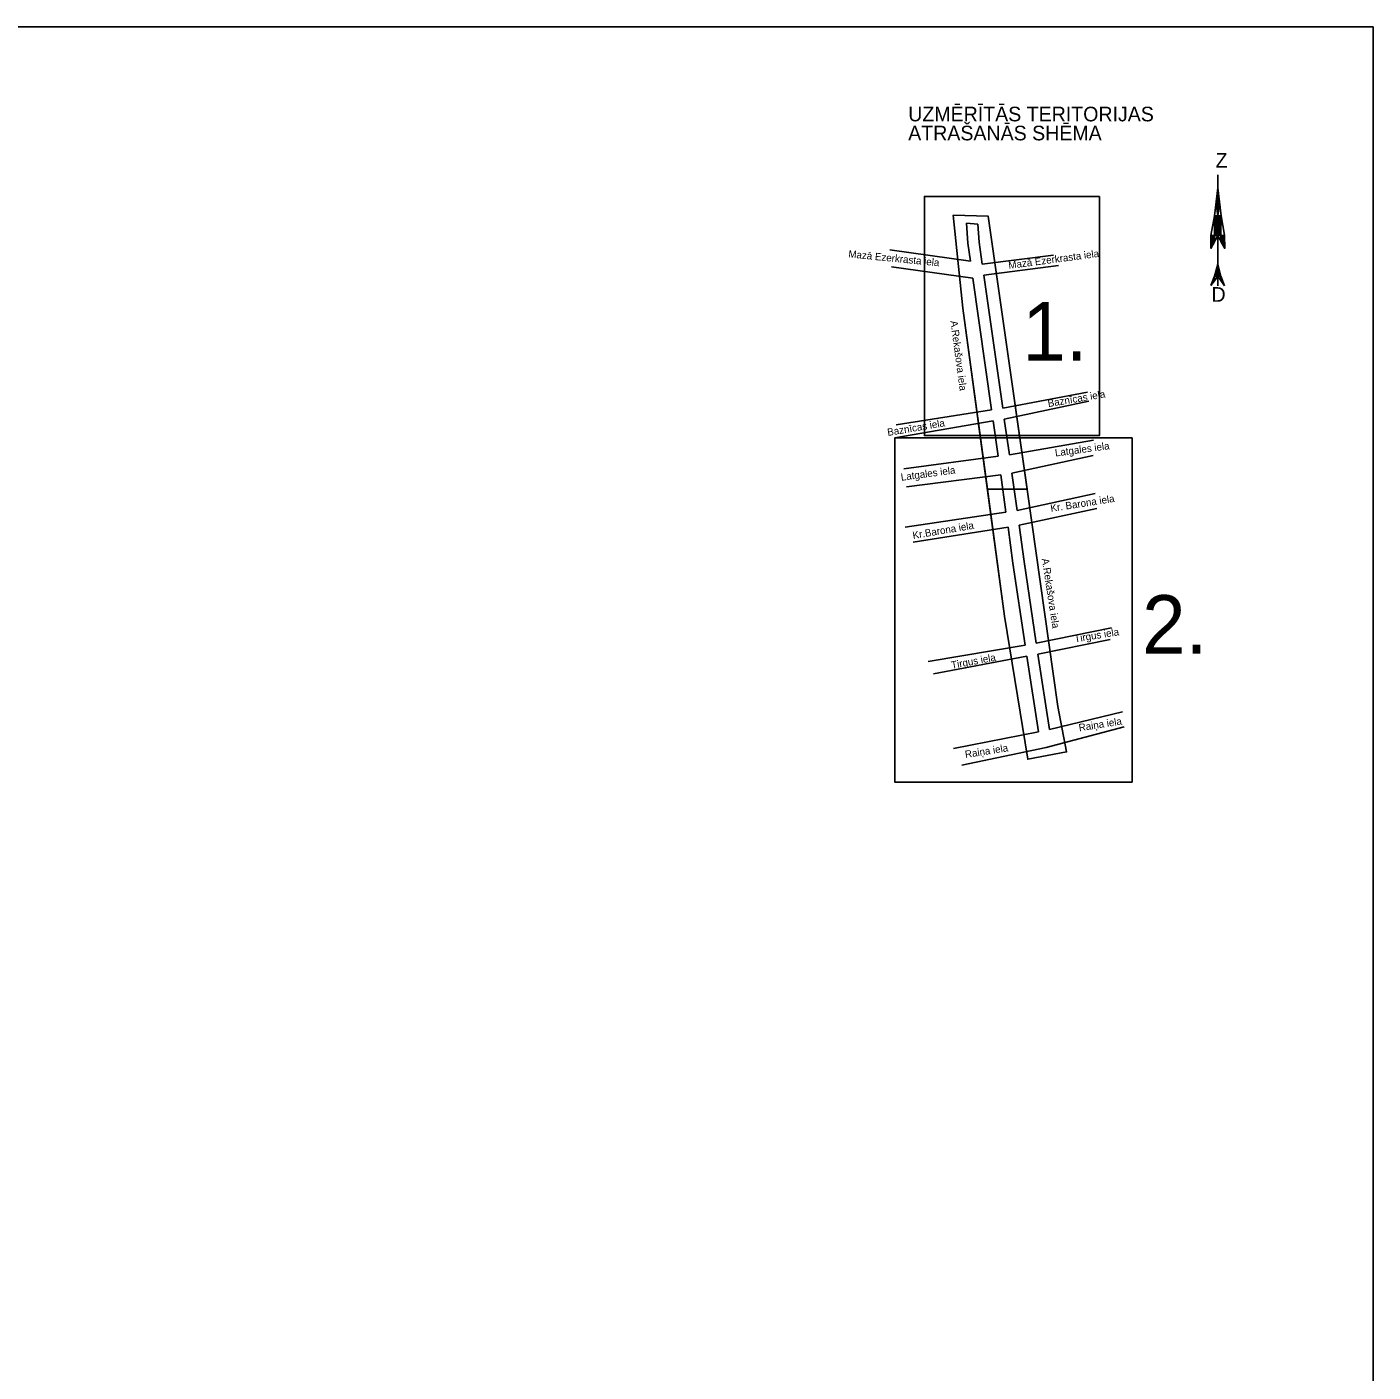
# Model space of a CAD drawing. Extents: x 728710 to 728960, y 272811 to 273475.
# Drawn here: x 728820.9 to 728912.9, y 273383.2 to 273475.1 of the extents above; entities that cross this region are included whole.
import ezdxf

# ---------------------------------------------------------------- set-up
doc = ezdxf.new("R2010")
doc.units = 0
doc.layers.add('RAMI_PLAN_####_TKST_#', color=7, linetype='Continuous')

msp = doc.modelspace()

# ---------------------------------------------------------------- linework, layer by layer
at = {"layer": 'RAMI_PLAN_####_TKST_#'}
for p, q in [((728902.305, 273465.008), (728902.305, 273464.128)), ((728902.087, 273462.204), (728902.305, 273464.12)), ((728902.305, 273464.12), (728902.181, 273463.03)), ((728902.268, 273463.788), (728902.335, 273463.855)), ((728902.275, 273463.851), (728902.329, 273463.906)), ((728902.282, 273463.915), (728902.324, 273463.957)), ((728902.289, 273463.979), (728902.318, 273464.008)), ((728902.297, 273464.043), (728902.312, 273464.059)), ((728902.304, 273464.107), (728902.307, 273464.11)), ((728902.305, 273464.12), (728902.52, 273462.209)), ((728902.428, 273463.033), (728902.305, 273464.12)), ((728902.303, 273462.206), (728902.181, 273463.03)), ((728902.181, 273463.03), (728902.303, 273462.206)), ((728902.182, 273463.023), (728902.404, 273463.245)), ((728902.187, 273463.085), (728902.398, 273463.296)), ((728902.189, 273462.974), (728902.41, 273463.194)), ((728902.195, 273463.149), (728902.392, 273463.347)), ((728902.197, 273462.925), (728902.415, 273463.143)), ((728902.202, 273463.213), (728902.387, 273463.398)), ((728902.204, 273462.875), (728902.421, 273463.093)), ((728902.209, 273463.277), (728902.381, 273463.449)), ((728902.211, 273462.826), (728902.427, 273463.042)), ((728902.216, 273463.341), (728902.375, 273463.499)), ((728902.218, 273462.777), (728902.419, 273462.978)), ((728902.224, 273463.404), (728902.37, 273463.55)), ((728902.231, 273463.468), (728902.364, 273463.601)), ((728902.238, 273463.532), (728902.358, 273463.652)), ((728902.246, 273463.596), (728902.352, 273463.703)), ((728902.253, 273463.66), (728902.347, 273463.754)), ((728902.26, 273463.724), (728902.341, 273463.804)), ((728902.428, 273463.033), (728902.303, 273462.206)), ((728902.303, 273462.206), (728902.428, 273463.033)), ((728901.82, 273460.867), (728902.087, 273462.204)), ((728902.087, 273462.204), (728902.077, 273460.888)), ((728902.084, 273461.875), (728902.302, 273462.093)), ((728902.084, 273461.818), (728902.302, 273462.037)), ((728902.085, 273462.046), (728902.245, 273462.206)), ((728902.085, 273461.989), (728902.302, 273462.206)), ((728902.085, 273461.932), (728902.302, 273462.15)), ((728902.086, 273462.103), (728902.188, 273462.205)), ((728902.086, 273462.16), (728902.13, 273462.204)), ((728902.087, 273462.204), (728902.303, 273462.206)), ((728902.226, 273462.728), (728902.409, 273462.911)), ((728902.233, 273462.678), (728902.399, 273462.844)), ((728902.24, 273462.629), (728902.389, 273462.778)), ((728902.247, 273462.58), (728902.379, 273462.711)), ((728902.255, 273462.53), (728902.369, 273462.644)), ((728902.262, 273462.481), (728902.359, 273462.578)), ((728902.269, 273462.432), (728902.349, 273462.511)), ((728902.277, 273462.382), (728902.339, 273462.444)), ((728902.284, 273462.333), (728902.328, 273462.378)), ((728902.291, 273462.284), (728902.318, 273462.311)), ((728902.298, 273462.235), (728902.308, 273462.245)), ((728902.303, 273462.206), (728902.298, 273457.431)), ((728902.302, 273462.135), (728902.52, 273461.917)), ((728902.302, 273462.078), (728902.52, 273461.86)), ((728902.302, 273462.021), (728902.52, 273461.804)), ((728902.303, 273462.206), (728902.52, 273462.209)), ((728902.303, 273462.191), (728902.52, 273461.973)), ((728902.343, 273462.207), (728902.52, 273462.03)), ((728902.399, 273462.208), (728902.52, 273462.086)), ((728902.455, 273462.208), (728902.52, 273462.143)), ((728902.511, 273462.209), (728902.52, 273462.199)), ((728902.52, 273462.209), (728902.519, 273460.884)), ((728902.52, 273462.209), (728902.763, 273460.879)), ((728885.896, 273461.644), (728885.121, 273461.699)), ((728902.077, 273460.907), (728902.301, 273461.131)), ((728902.078, 273461.021), (728902.302, 273461.244)), ((728902.078, 273460.964), (728902.301, 273461.187)), ((728902.079, 273461.192), (728902.302, 273461.414)), ((728902.079, 273461.135), (728902.302, 273461.357)), ((728902.079, 273461.078), (728902.302, 273461.301)), ((728902.08, 273461.306), (728902.302, 273461.527)), ((728902.08, 273461.249), (728902.302, 273461.47)), ((728902.081, 273461.476), (728902.302, 273461.697)), ((728902.081, 273461.419), (728902.302, 273461.64)), ((728902.081, 273461.362), (728902.302, 273461.584)), ((728902.082, 273461.59), (728902.302, 273461.81)), ((728902.082, 273461.533), (728902.302, 273461.754)), ((728902.083, 273461.761), (728902.302, 273461.98)), ((728902.083, 273461.704), (728902.302, 273461.923)), ((728902.083, 273461.647), (728902.302, 273461.867)), ((728902.301, 273461.174), (728902.519, 273460.956)), ((728902.301, 273461.117), (728902.519, 273460.9)), ((728902.302, 273461.965), (728902.52, 273461.747)), ((728902.302, 273461.908), (728902.52, 273461.691)), ((728902.302, 273461.852), (728902.52, 273461.634)), ((728902.302, 273461.795), (728902.52, 273461.578)), ((728902.302, 273461.739), (728902.52, 273461.521)), ((728902.302, 273461.682), (728902.52, 273461.465)), ((728902.302, 273461.626), (728902.519, 273461.408)), ((728902.302, 273461.569), (728902.519, 273461.352)), ((728902.302, 273461.513), (728902.519, 273461.295)), ((728902.302, 273461.456), (728902.519, 273461.239)), ((728902.302, 273461.4), (728902.519, 273461.182)), ((728902.302, 273461.343), (728902.519, 273461.126)), ((728902.302, 273461.287), (728902.519, 273461.069)), ((728902.302, 273461.23), (728902.519, 273461.013)), ((728901.82, 273460.867), (728902.301, 273460.873)), ((728902.077, 273460.87), (728901.82, 273460.867)), ((728901.82, 273460.867), (728901.833, 273459.973)), ((728901.82, 273460.867), (728901.833, 273459.973)), ((728901.821, 273460.818), (728901.87, 273460.868)), ((728901.822, 273460.707), (728901.985, 273460.869)), ((728901.822, 273460.762), (728901.928, 273460.868)), ((728901.823, 273460.651), (728902.042, 273460.87)), ((728901.824, 273460.595), (728902.077, 273460.848)), ((728901.825, 273460.539), (728902.077, 273460.792)), ((728901.826, 273460.484), (728902.077, 273460.735)), ((728901.827, 273460.428), (728902.077, 273460.679)), ((728901.827, 273460.372), (728902.077, 273460.622)), ((728901.828, 273460.316), (728902.077, 273460.566)), ((728901.829, 273460.261), (728902.077, 273460.509)), ((728901.83, 273460.205), (728902.077, 273460.453)), ((728901.831, 273460.149), (728902.026, 273460.345)), ((728901.831, 273460.093), (728901.965, 273460.227)), ((728901.833, 273459.973), (728902.301, 273460.873)), ((728901.833, 273459.973), (728902.077, 273460.443)), ((728902.077, 273460.443), (728902.077, 273460.888)), ((728902.077, 273460.443), (728902.077, 273460.87)), ((728902.098, 273460.871), (728902.301, 273461.074)), ((728902.155, 273460.871), (728902.301, 273461.017)), ((728902.213, 273460.872), (728902.301, 273460.961)), ((728902.27, 273460.873), (728902.301, 273460.904)), ((728902.301, 273461.061), (728902.486, 273460.876)), ((728902.301, 273461.004), (728902.431, 273460.875)), ((728902.301, 273460.948), (728902.375, 273460.874)), ((728902.301, 273460.891), (728902.319, 273460.874)), ((728902.301, 273460.873), (728902.763, 273460.879)), ((728902.776, 273459.973), (728902.301, 273460.873)), ((728902.516, 273460.467), (728902.519, 273460.884)), ((728902.519, 273460.876), (728902.516, 273460.467)), ((728902.516, 273460.59), (728902.771, 273460.335)), ((728902.516, 273460.534), (728902.772, 273460.278)), ((728902.516, 273460.477), (728902.772, 273460.221)), ((728902.516, 273460.467), (728902.776, 273459.973)), ((728902.517, 273460.702), (728902.769, 273460.45)), ((728902.517, 273460.646), (728902.77, 273460.393)), ((728902.518, 273460.814), (728902.767, 273460.565)), ((728902.518, 273460.758), (728902.768, 273460.508)), ((728902.763, 273460.879), (728902.519, 273460.876)), ((728902.519, 273460.87), (728902.767, 273460.622)), ((728902.567, 273460.37), (728902.773, 273460.163)), ((728902.569, 273460.877), (728902.766, 273460.68)), ((728902.625, 273460.878), (728902.765, 273460.737)), ((728902.63, 273460.25), (728902.774, 273460.106)), ((728902.681, 273460.878), (728902.764, 273460.795)), ((728902.736, 273460.879), (728902.763, 273460.852)), ((728902.776, 273459.973), (728902.763, 273460.879)), ((728902.776, 273459.973), (728902.763, 273460.879)), ((728901.832, 273460.038), (728901.904, 273460.109)), ((728901.833, 273459.982), (728901.842, 273459.991)), ((728902.693, 273460.13), (728902.775, 273460.049)), ((728902.756, 273460.01), (728902.776, 273459.991)), ((728902.298, 273458.914), (728902.077, 273458.093)), ((728902.087, 273458.128), (728902.299, 273458.34)), ((728902.107, 273458.206), (728902.299, 273458.397)), ((728902.128, 273458.283), (728902.299, 273458.453)), ((728902.149, 273458.36), (728902.299, 273458.51)), ((728902.17, 273458.438), (728902.299, 273458.567)), ((728902.191, 273458.515), (728902.299, 273458.623)), ((728902.211, 273458.592), (728902.299, 273458.68)), ((728902.232, 273458.67), (728902.299, 273458.736)), ((728902.253, 273458.747), (728902.299, 273458.793)), ((728902.274, 273458.824), (728902.299, 273458.85)), ((728902.294, 273458.902), (728902.299, 273458.906)), ((728902.298, 273458.914), (728902.519, 273458.093)), ((728902.299, 273458.889), (728902.306, 273458.882)), ((728902.299, 273458.833), (728902.327, 273458.805)), ((728902.299, 273458.776), (728902.348, 273458.728)), ((728902.299, 273458.72), (728902.369, 273458.65)), ((728902.299, 273458.663), (728902.39, 273458.573)), ((728902.299, 273458.607), (728902.41, 273458.495)), ((728902.299, 273458.55), (728902.431, 273458.418)), ((728902.299, 273458.494), (728902.452, 273458.34)), ((728902.299, 273458.437), (728902.473, 273458.263)), ((728902.299, 273458.381), (728902.494, 273458.185)), ((728902.299, 273458.324), (728902.515, 273458.108)), ((728901.823, 273457.446), (728902.077, 273458.093)), ((728902.077, 273458.093), (728901.823, 273457.446)), ((728902.077, 273457.774), (728901.823, 273457.446)), ((728901.823, 273457.446), (728902.077, 273457.774)), ((728901.83, 273457.465), (728901.862, 273457.497)), ((728901.867, 273457.558), (728902.058, 273457.749)), ((728901.904, 273457.652), (728902.077, 273457.825)), ((728901.94, 273457.745), (728902.077, 273457.882)), ((728901.977, 273457.838), (728902.077, 273457.938)), ((728902.014, 273457.931), (728902.077, 273457.995)), ((728902.05, 273458.025), (728902.077, 273458.052)), ((728902.077, 273458.093), (728902.298, 273458.097)), ((728902.077, 273457.774), (728902.298, 273458.097)), ((728902.077, 273458.093), (728902.077, 273457.774)), ((728902.077, 273457.774), (728902.077, 273458.093)), ((728902.109, 273458.094), (728902.298, 273458.283)), ((728902.166, 273458.095), (728902.298, 273458.227)), ((728902.224, 273458.096), (728902.298, 273458.17)), ((728902.281, 273458.097), (728902.298, 273458.114)), ((728902.298, 273458.268), (728902.472, 273458.094)), ((728902.298, 273458.211), (728902.415, 273458.095)), ((728902.298, 273458.155), (728902.357, 273458.096)), ((728902.298, 273458.098), (728902.3, 273458.097)), ((728902.519, 273458.093), (728902.298, 273458.097)), ((728902.298, 273458.097), (728902.519, 273457.779)), ((728902.519, 273458.093), (728902.767, 273457.431)), ((728902.519, 273457.779), (728902.519, 273458.093)), ((728902.767, 273457.431), (728902.519, 273458.093)), ((728902.519, 273458.093), (728902.519, 273457.779)), ((728902.519, 273458.091), (728902.52, 273458.09)), ((728902.519, 273458.035), (728902.554, 273457.999)), ((728902.519, 273457.978), (728902.588, 273457.909)), ((728902.519, 273457.921), (728902.622, 273457.819)), ((728902.519, 273457.865), (728902.655, 273457.728)), ((728902.519, 273457.808), (728902.689, 273457.638)), ((728902.767, 273457.431), (728902.519, 273457.779)), ((728902.519, 273457.779), (728902.767, 273457.431)), ((728902.586, 273457.684), (728902.723, 273457.547)), ((728902.726, 273457.488), (728902.757, 273457.457)), ((728889.262, 273443.524), (728887.585, 273455.327)), ((728886.554, 273443.524), (728889.262, 273443.524)), ((728889.262, 273443.524), (728886.554, 273443.524)), ((728886.554, 273443.524), (728887.726, 273434.842))]:
    msp.add_line(p, q, dxfattribs=at)
for points in [[(728728.89, 273202.048), (728728.89, 273475.126), (728912.915, 273475.126), (728912.915, 273202.048)], [(728894.211, 273463.543), (728882.251, 273463.543), (728882.251, 273447.186), (728894.211, 273447.186)], [(728889.31, 273425.063), (728891.962, 273425.567), (728891.371, 273428.674), (728889.266, 273443.491), (728887.585, 273455.327), (728886.61, 273462.183), (728884.224, 273462.249), (728884.882, 273455.909), (728887.726, 273434.842)], [(728896.444, 273447.034), (728880.225, 273447.034), (728880.225, 273423.504), (728896.444, 273423.504)]]:
    msp.add_lwpolyline(points, close=True, dxfattribs=at)
for points in [[(728887.585, 273455.327), (728886.61, 273462.183), (728884.224, 273462.249), (728884.882, 273455.909), (728886.554, 273443.524)], [(728885.396, 273459.122), (728885.226, 273460.334), (728885.121, 273461.699)], [(728886.2, 273458.915), (728885.99, 273460.416), (728885.896, 273461.644)], [(728885.396, 273459.122), (728879.874, 273459.891)], [(728891.076, 273459.518), (728886.2, 273458.915)], [(728885.562, 273457.947), (728880.006, 273458.728)], [(728891.405, 273458.816), (728886.308, 273458.152)], [(728886.84, 273448.958), (728885.562, 273457.947)], [(728887.6, 273449.071), (728886.308, 273458.152)], [(728887.6, 273449.071), (728893.4, 273450.15)], [(728887.708, 273448.311), (728893.487, 273449.535)], [(728886.948, 273448.198), (728880.225, 273447.034)], [(728886.84, 273448.958), (728880.313, 273447.934)], [(728886.948, 273448.198), (728887.294, 273445.771)], [(728887.708, 273448.311), (728888.054, 273445.878)], [(728893.816, 273446.881), (728888.054, 273445.878)], [(728887.294, 273445.771), (728880.839, 273444.906)], [(728893.772, 273445.828), (728888.231, 273444.61)], [(728888.231, 273444.61), (728888.579, 273442.074)], [(728887.471, 273444.503), (728881.014, 273443.678)], [(728887.471, 273444.503), (728887.822, 273441.942)], [(728887.726, 273434.842), (728889.31, 273425.063), (728891.962, 273425.567), (728891.371, 273428.674), (728889.266, 273443.491), (728889.262, 273443.524)], [(728893.926, 273443.239), (728888.579, 273442.074)], [(728887.822, 273441.942), (728880.927, 273440.935)], [(728894.035, 273442.208), (728888.718, 273441.059)], [(728887.961, 273440.927), (728881.475, 273439.904)], [(728887.961, 273440.927), (728888.297, 273438.477), (728889.128, 273432.869)], [(728888.718, 273441.059), (728889.057, 273438.586), (728889.885, 273433.002)], [(728895.031, 273434.036), (728889.885, 273433.002)], [(728889.128, 273432.869), (728882.493, 273431.754)], [(728894.944, 273433.246), (728890, 273432.242)], [(728889.243, 273432.109), (728882.865, 273430.898)], [(728889.243, 273432.109), (728890.043, 273426.935)], [(728890, 273432.242), (728890.797, 273427.084)], [(728895.777, 273428.309), (728890.797, 273427.084)], [(728895.908, 273427.278), (728890.569, 273425.868), (728884.795, 273424.664)], [(728890.043, 273426.935), (728884.246, 273425.787)]]:
    msp.add_lwpolyline(points, dxfattribs=at)

# ---------------------------------------------------------------- texts
for s, height, rotation, p in [('UZMĒRĪTĀS TERITORIJAS ', 1, 359.99995, (728881.14, 273468.671)), ('ATRAŠANĀS SHĒMA', 1, 359.99995, (728881.14, 273467.371)), ('Z', 1, 359.99995, (728902.148, 273465.505)), ('Mazā Ezerkrasta iela', 0.5, 354.37261, (728877.033, 273459.371)), ('Mazā Ezerkrasta iela', 0.5, 7.62348, (728888.023, 273458.578)), ('D', 1, 359.99995, (728901.87, 273456.337)), ('A.Rekašova iela', 0.5, 277.641, (728884.02, 273455.015)), ('Baznīcas iela', 0.5, 9.60838, (728890.719, 273449.136)), ('Baznīcas iela', 0.5, 9.60838, (728879.753, 273447.16)), ('Latgales iela', 0.5, 7.723, (728891.205, 273445.753)), ('Latgales iela', 0.5, 7.723, (728880.669, 273444.096)), ('Kr. Barona iela', 0.5, 8.96758, (728890.902, 273441.968)), ('Kr.Barona iela', 0.5, 9.638, (728881.481, 273440.113)), ('A.Rekašova iela', 0.5, 278.74, (728890.266, 273438.755)), ('Tirgus iela', 0.5, 9.194, (728892.537, 273433.05)), ('Tirgus iela', 0.5, 10.472, (728884.126, 273431.24)), ('Raiņa iela', 0.5, 9.06589, (728892.836, 273426.967)), ('Raiņa iela', 0.5, 9.06589, (728885.06, 273425.141))]:
    msp.add_text(s, height=height, rotation=rotation, dxfattribs=at).set_placement(p)
for s, p in [('1.', (728888.934, 273452.315)), ('2.', (728897.128, 273432.277))]:
    msp.add_text(s, height=4, dxfattribs=at).set_placement(p)

doc.saveas('drawing.dxf')
